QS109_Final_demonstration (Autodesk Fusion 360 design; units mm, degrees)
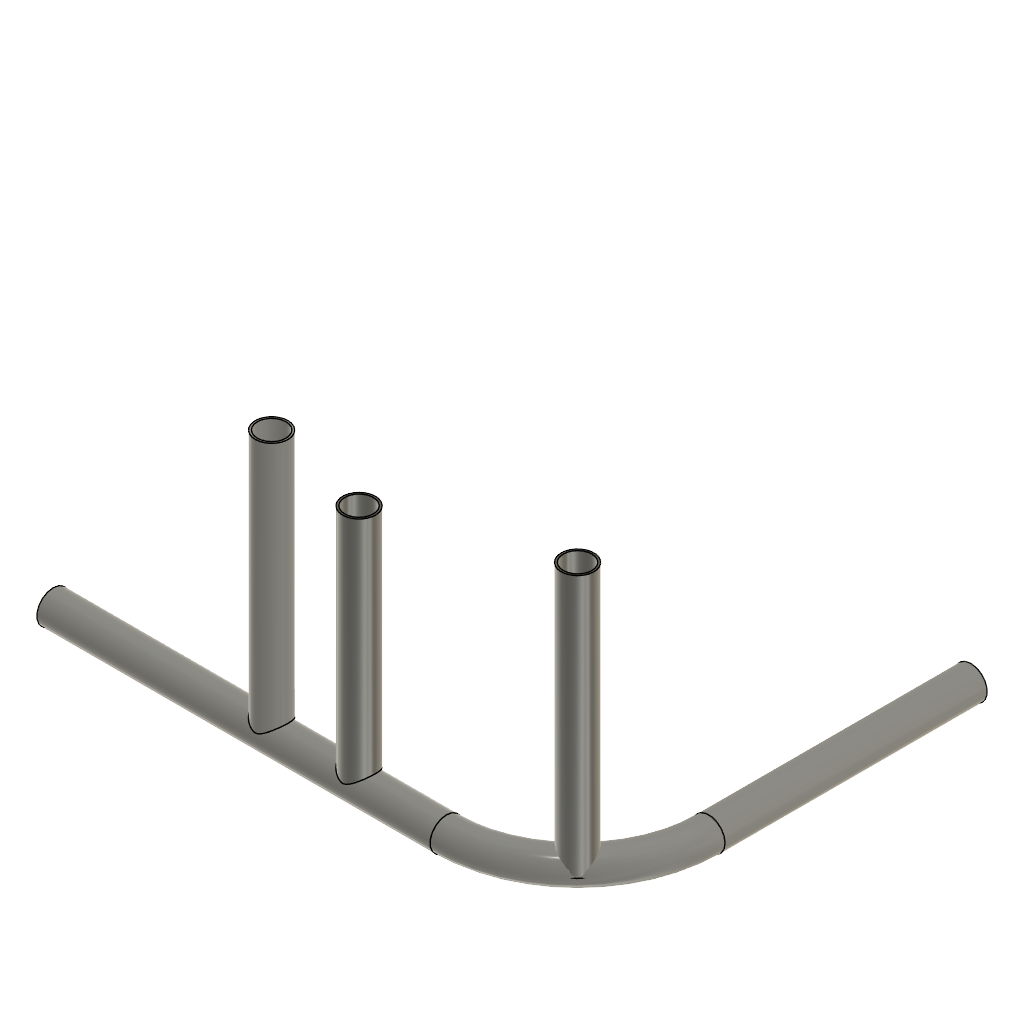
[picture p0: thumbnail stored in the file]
description: Part Number
part number: 2026-10-26-11-38-19-526
parameter "OD_DEMO_ONLY_1_5_x_095_R6" = 38.1
parameter "Wall_DEMO_ONLY_1_5_x_095_R6" = 2.413
base_feature "Base Feature1" bodies "H1 Bent host", "I1 Imported coped brace"
sketch "Tube points" plane through (0, 0, 0) normal (0, 0, 1) x axis (1, 0, 0)
sketch "TubePoints" plane through (0, 0, 0) normal (0, 0, 1) x axis (1, 0, 0)
work_plane "WorkPlane1" ExtraOffset 0
sketch "Sketch3" plane through (564.9631, 44.6369, 0) normal (0, 0, 1) x axis (0, 1, 0)
  circle C1 centre (0, 0) radius 19.05
  circle C2 centre (0, 0) radius 16.637
sketch "TubePoints (1)" plane through (0, 0, 0) normal (0, 0, 1) x axis (1, 0, 0)
work_plane "WorkPlane2" ExtraOffset 0
sketch "Sketch5" plane through (355.6, 0, 0) normal (0, 0, 1) x axis (0, 1, 0)
  circle C1 centre (0, 0) radius 19.05
  circle C2 centre (0, 0) radius 16.637
sketch "TubePoints (2)" plane through (0, 0, 0) normal (0, 0, 1) x axis (1, 0, 0)
work_plane "WorkPlane3" ExtraOffset 0
sketch "Sketch7" plane through (564.9631, 44.6369, 0) normal (0, 0, 1) x axis (0, 1, 0)
  circle C1 centre (0, 0) radius 19.05
  circle C2 centre (0, 0) radius 16.637
  dimension "d21" diameter C1 = 38.1 (= "OD_DEMO_ONLY_1_5_x_095_R6")
  dimension "d22" diameter C2 = 33.274 (= "OD_DEMO_ONLY_1_5_x_095_R6 - 2 * Wall_DEMO_ONLY_1_5_x_095_R6")
sweep "Sweep3" sketch "Sketch7" TwistAngle 0 TaperAngle 0 bodies "B1 Bend follower"
sketch "TubePoints (3)" plane through (0, 0, 0) normal (0, 0, 1) x axis (1, 0, 0)
work_plane "WorkPlane4" ExtraOffset 0
sketch "Sketch9" plane through (355.6, 0, 0) normal (0, 0, 1) x axis (0, 1, 0)
  circle C1 centre (0, 0) radius 19.05
  circle C2 centre (0, 0) radius 16.637
  dimension "d31" diameter C1 = 38.1 (= "OD_DEMO_ONLY_1_5_x_095_R6")
  dimension "d32" diameter C2 = 33.274 (= "OD_DEMO_ONLY_1_5_x_095_R6 - 2 * Wall_DEMO_ONLY_1_5_x_095_R6")
sweep "Sweep4" sketch "Sketch9" TwistAngle 0 TaperAngle 0 bodies "B2 Straight joint"
base_feature "Base Feature2"
surface_stitch "SurfaceStitch1" StitchingTolerence 0.01 bodies "normcope_B2_Straight_joint_A"
split "Split1" bodies "B2 Straight joint"
remove_body "RemoveBody1"
remove_body "RemoveBody2"
named bodies: "H1 Bent host", "I1 Imported coped brace", "B1 Bend follower", "B2 Straight joint", "normcope_B2_Straight_joint_A"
